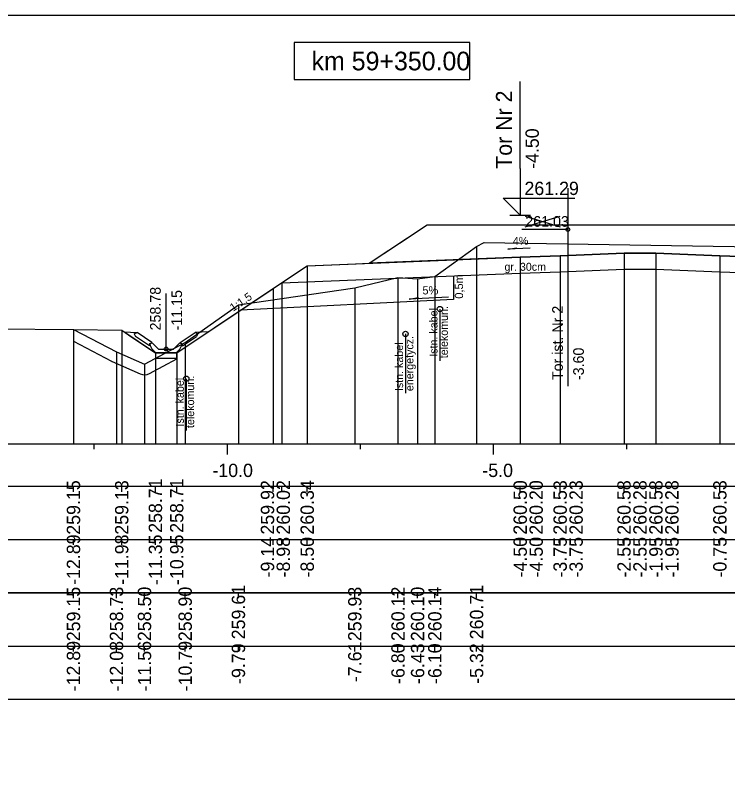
# Model space of a CAD drawing. Extents: x 6516023 to 6560129, y 5513077 to 5529206.
# Drawn here: x 6517566.48 to 6517579.86, y 5514532.41 to 5514546.66 of the extents above; entities that cross this region are included whole.
import ezdxf

# ---------------------------------------------------------------- set-up
doc = ezdxf.new("R2010")
doc.units = 0
for name, color, linetype in [('IR_default', 7, 'Continuous'), ('TOR_PRZEK_P-kable', 7, 'Continuous'), ('TOR_PRZEK_P-komponent', 7, 'Continuous'), ('TOR_PRZEK_P-odwodnienie', 7, 'Continuous'), ('TOR_PRZEK_P-opisy', 7, 'Continuous'), ('TOR_PRZEK_P-schodkowanie+wymiana', 7, 'Continuous'), ('TOR_PRZEK_P-tabelka istniejace', 7, 'Continuous'), ('TOR_PRZEK_P-tabelka projektowane', 7, 'Continuous'), ('TOR_PRZEK_P-teren istniejacy', 7, 'Continuous'), ('TOR_PRZEK_P-tory istniejace', 7, 'Continuous'), ('TOR_PRZEK_P-tory projektowane', 7, 'Continuous'), ('TOR_PRZEK_P-uklad odniesienia', 7, 'Continuous'), ('TOR_PRZEK_P-warstwa ochronna I', 7, 'Continuous'), ('TOR_PRZEK_P-warstwa ochronna II', 7, 'Continuous'), ('TOR_PS_T-skarpy projektowane', 7, 'Continuous'), ('TOR_RAMKI-ramka+tabelka 1', 7, 'Continuous')]:
    doc.layers.add(name, color=color, linetype=linetype)

msp = doc.modelspace()

# ---------------------------------------------------------------- linework, layer by layer
at = {"layer": 'IR_default'}
msp.add_lwpolyline([(6517567.573, 5514540.755), (6517568.479, 5514540.737), (6517568.604, 5514540.653), (6517568.728, 5514540.571), (6517569.112, 5514540.315), (6517569.422, 5514540.315), (6517569.512, 5514540.315), (6517570.919, 5514541.253), (6517571.323, 5514541.523), (6517571.324, 5514541.523), (6517571.325, 5514541.523), (6517571.82, 5514541.853), (6517571.963, 5514541.948), (6517572.867, 5514541.984), (6517573.128, 5514541.995), (6517573.97, 5514542.556), (6517574.213, 5514542.718), (6517576.929, 5514542.718), (6517577.713, 5514542.718), (6517578.489, 5514542.718), (6517578.713, 5514542.718), (6517581.429, 5514542.718)], dxfattribs=at)
at = {"layer": 'TOR_PRZEK_P-kable'}
for p, q in [((6517574.455, 5514541.137), (6517574.455, 5514540.164)), ((6517573.809, 5514540.669), (6517573.809, 5514539.559)), ((6517569.691, 5514539.828), (6517569.691, 5514538.854))]:
    msp.add_line(p, q, dxfattribs=at)
for centre in [(6517574.455, 5514541.137), (6517573.809, 5514540.669), (6517569.691, 5514539.828)]:
    msp.add_circle(centre, 0.05, dxfattribs=at)
at = {"layer": 'TOR_PRZEK_P-komponent'}
msp.add_lwpolyline([(6517574.213, 5514542.718), (6517577.713, 5514542.718), (6517578.713, 5514542.718), (6517582.213, 5514542.718), (6517582.763, 5514542.719), (6517586.263, 5514542.719), (6517587.608, 5514541.822), (6517583.763, 5514541.976), (6517580.463, 5514542.108), (6517579.713, 5514542.138), (6517578.513, 5514542.186), (6517577.913, 5514542.186), (6517576.713, 5514542.138), (6517575.963, 5514542.108), (6517573.128, 5514541.995)], close=True, dxfattribs=at)
at = {"layer": 'TOR_PRZEK_P-odwodnienie'}
for p, q in [((6517569.312, 5514540.385), (6517569.312, 5514541.429)), ((6517569.047, 5514540.511), (6517568.767, 5514540.698)), ((6517569.576, 5514540.511), (6517569.857, 5514540.698)), ((6517569.003, 5514540.444), (6517568.741, 5514540.618)), ((6517569.621, 5514540.444), (6517569.882, 5514540.618)), ((6517569.014, 5514540.461), (6517569.003, 5514540.444)), ((6517569.004, 5514540.48), (6517569.052, 5514540.504)), ((6517569.047, 5514540.511), (6517569.039, 5514540.498)), ((6517569.172, 5514540.385), (6517569.052, 5514540.504)), ((6517569.172, 5514540.385), (6517569.452, 5514540.385)), ((6517569.452, 5514540.385), (6517569.572, 5514540.504)), ((6517569.572, 5514540.504), (6517569.619, 5514540.48)), ((6517569.576, 5514540.511), (6517569.585, 5514540.498)), ((6517569.61, 5514540.461), (6517569.621, 5514540.444)), ((6517569.122, 5514540.315), (6517569.502, 5514540.315))]:
    msp.add_line(p, q, dxfattribs=at)
for points in [[(6517568.52, 5514540.709), (6517568.767, 5514540.698)], [(6517568.716, 5514540.671), (6517568.767, 5514540.698)], [(6517568.716, 5514540.671), (6517568.741, 5514540.618)], [(6517570.103, 5514540.709), (6517569.857, 5514540.698)], [(6517569.907, 5514540.671), (6517569.857, 5514540.698)], [(6517569.907, 5514540.671), (6517569.882, 5514540.618)], [(6517569.039, 5514540.498), (6517569.004, 5514540.48)], [(6517569.052, 5514540.385), (6517569.004, 5514540.48)], [(6517569.004, 5514540.48), (6517569.014, 5514540.461)], [(6517569.122, 5514540.315), (6517569.052, 5514540.385)], [(6517569.502, 5514540.315), (6517569.572, 5514540.385)], [(6517569.572, 5514540.385), (6517569.619, 5514540.48)], [(6517569.585, 5514540.498), (6517569.62, 5514540.48)], [(6517569.62, 5514540.48), (6517569.61, 5514540.461)], [(6517569.512, 5514540.315), (6517569.112, 5514540.315), (6517569.112, 5514540.215), (6517569.512, 5514540.215), (6517569.512, 5514540.315)], [(6517569.512, 5514540.315), (6517569.511, 5514540.316), (6517569.512, 5514540.315), (6517569.511, 5514540.315), (6517569.512, 5514540.315), (6517569.512, 5514540.315), (6517569.512, 5514540.315), (6517569.512, 5514540.316)], [(6517569.512, 5514540.315), (6517569.511, 5514540.315), (6517569.512, 5514540.315), (6517569.511, 5514540.314), (6517569.512, 5514540.315), (6517569.512, 5514540.314), (6517569.512, 5514540.315), (6517569.512, 5514540.315)]]:
    msp.add_lwpolyline(points, dxfattribs=at)
msp.add_circle((6517569.312, 5514540.385), 0.035, dxfattribs=at)
at = {"layer": 'TOR_PRZEK_P-opisy'}
msp.add_lwpolyline([(6517576.149, 5514542.277), (6517575.731, 5514542.258), (6517575.899, 5514542.286)], dxfattribs=at)
at = {"layer": 'TOR_PRZEK_P-schodkowanie+wymiana'}
for p, q in [((6517574.708, 5514541.758), (6517574.708, 5514541.315)), ((6517574.708, 5514541.315), (6517570.712, 5514541.115)), ((6517568.301, 5514540.151), (6517568.826, 5514539.92)), ((6517569.001, 5514539.926), (6517569.512, 5514540.199))]:
    msp.add_line(p, q, dxfattribs=at)
msp.add_lwpolyline([(6517567.573, 5514540.53), (6517568.289, 5514540.156)], dxfattribs=at)
for centre, start, end in [((6517568.381, 5514540.334), 242.4451, 246.2607), ((6517568.907, 5514540.103), 246.2607, 298.0902)]:
    msp.add_arc(centre, 0.2, start, end, dxfattribs=at)
at = {"layer": 'TOR_PRZEK_P-tabelka istniejace'}
for p, q in [((6517567.573, 5514535.706), (6517567.573, 5514535.806)), ((6517568.381, 5514535.706), (6517568.381, 5514535.806)), ((6517568.907, 5514535.706), (6517568.907, 5514535.806)), ((6517569.671, 5514535.706), (6517569.671, 5514535.806)), ((6517570.671, 5514535.706), (6517570.671, 5514535.806)), ((6517572.857, 5514535.706), (6517572.857, 5514535.806)), ((6517573.668, 5514535.706), (6517573.668, 5514535.806)), ((6517574.036, 5514535.706), (6517574.036, 5514535.806)), ((6517574.36, 5514535.706), (6517574.36, 5514535.806)), ((6517575.144, 5514535.706), (6517575.144, 5514535.806)), ((6517541.663, 5514534.806), (6517625.463, 5514534.806)), ((6517567.573, 5514534.706), (6517567.573, 5514534.806)), ((6517568.381, 5514534.706), (6517568.381, 5514534.806)), ((6517568.907, 5514534.706), (6517568.907, 5514534.806)), ((6517569.671, 5514534.706), (6517569.671, 5514534.806)), ((6517570.671, 5514534.706), (6517570.671, 5514534.806)), ((6517572.857, 5514534.706), (6517572.857, 5514534.806)), ((6517573.668, 5514534.706), (6517573.668, 5514534.806)), ((6517574.036, 5514534.706), (6517574.036, 5514534.806)), ((6517574.36, 5514534.706), (6517574.36, 5514534.806)), ((6517575.144, 5514534.706), (6517575.144, 5514534.806))]:
    msp.add_line(p, q, dxfattribs=at)
for points in [[(6517575.144, 5514542.314), (6517575.144, 5514538.806), (6517575.144, 5514538.676), (6517575.144, 5514538.606)], [(6517573.668, 5514541.73), (6517573.668, 5514538.806), (6517573.668, 5514538.676), (6517573.668, 5514538.606)], [(6517574.036, 5514541.703), (6517574.036, 5514538.806), (6517574.036, 5514538.676), (6517574.036, 5514538.606)], [(6517574.36, 5514541.745), (6517574.36, 5514538.806), (6517574.36, 5514538.676), (6517574.36, 5514538.606)], [(6517572.857, 5514541.536), (6517572.857, 5514538.806), (6517572.857, 5514538.676), (6517572.857, 5514538.606)], [(6517570.671, 5514541.215), (6517570.671, 5514538.806), (6517570.671, 5514538.676), (6517570.671, 5514538.606)], [(6517567.573, 5514540.755), (6517567.573, 5514538.806), (6517567.573, 5514538.676), (6517567.573, 5514538.606)], [(6517569.671, 5514540.51), (6517569.671, 5514538.806), (6517569.671, 5514538.676), (6517569.671, 5514538.606)], [(6517568.381, 5514540.334), (6517568.381, 5514538.806), (6517568.381, 5514538.676), (6517568.381, 5514538.606)], [(6517568.907, 5514540.103), (6517568.907, 5514538.806), (6517568.907, 5514538.676), (6517568.907, 5514538.606)]]:
    msp.add_lwpolyline(points, dxfattribs=at)
msp.add_lwpolyline([(6517541.663, 5514535.806), (6517541.663, 5514533.806), (6517625.463, 5514533.806), (6517625.463, 5514535.806)], close=True, dxfattribs=at)
at = {"layer": 'TOR_PRZEK_P-tabelka projektowane'}
for p, q in [((6517567.573, 5514537.706), (6517567.573, 5514537.806)), ((6517568.479, 5514537.706), (6517568.479, 5514537.806)), ((6517569.112, 5514537.706), (6517569.112, 5514537.806)), ((6517569.512, 5514537.706), (6517569.512, 5514537.806)), ((6517571.323, 5514537.706), (6517571.323, 5514537.806)), ((6517571.484, 5514537.706), (6517571.484, 5514537.806)), ((6517571.963, 5514537.706), (6517571.963, 5514537.806)), ((6517575.963, 5514537.706), (6517575.963, 5514537.806)), ((6517575.963, 5514537.706), (6517575.963, 5514537.806)), ((6517576.713, 5514537.706), (6517576.713, 5514537.806)), ((6517576.713, 5514537.706), (6517576.713, 5514537.806)), ((6517577.913, 5514537.706), (6517577.913, 5514537.806)), ((6517577.913, 5514537.706), (6517577.913, 5514537.806)), ((6517578.513, 5514537.706), (6517578.513, 5514537.806)), ((6517578.513, 5514537.706), (6517578.513, 5514537.806)), ((6517579.713, 5514537.706), (6517579.713, 5514537.806)), ((6517579.713, 5514537.706), (6517579.713, 5514537.806)), ((6517541.663, 5514536.806), (6517625.463, 5514536.806)), ((6517567.573, 5514536.706), (6517567.573, 5514536.806)), ((6517568.479, 5514536.706), (6517568.479, 5514536.806)), ((6517569.112, 5514536.706), (6517569.112, 5514536.806)), ((6517569.512, 5514536.706), (6517569.512, 5514536.806)), ((6517571.323, 5514536.706), (6517571.323, 5514536.806)), ((6517571.484, 5514536.706), (6517571.484, 5514536.806)), ((6517571.963, 5514536.706), (6517571.963, 5514536.806)), ((6517575.963, 5514536.706), (6517575.963, 5514536.806)), ((6517575.963, 5514536.706), (6517575.963, 5514536.806)), ((6517576.713, 5514536.706), (6517576.713, 5514536.806)), ((6517576.713, 5514536.706), (6517576.713, 5514536.806)), ((6517577.913, 5514536.706), (6517577.913, 5514536.806)), ((6517577.913, 5514536.706), (6517577.913, 5514536.806)), ((6517578.513, 5514536.706), (6517578.513, 5514536.806)), ((6517578.513, 5514536.706), (6517578.513, 5514536.806)), ((6517579.713, 5514536.706), (6517579.713, 5514536.806)), ((6517579.713, 5514536.706), (6517579.713, 5514536.806))]:
    msp.add_line(p, q, dxfattribs=at)
for points in [[(6517575.963, 5514542.108), (6517575.963, 5514538.806), (6517575.963, 5514538.676), (6517575.963, 5514538.606)], [(6517576.713, 5514542.138), (6517576.713, 5514538.806), (6517576.713, 5514538.676), (6517576.713, 5514538.606)], [(6517577.913, 5514542.186), (6517577.913, 5514538.806), (6517577.913, 5514538.676), (6517577.913, 5514538.606)], [(6517578.513, 5514542.186), (6517578.513, 5514538.806), (6517578.513, 5514538.676), (6517578.513, 5514538.606)], [(6517579.713, 5514542.138), (6517579.713, 5514538.806), (6517579.713, 5514538.676), (6517579.713, 5514538.606)], [(6517571.963, 5514541.948), (6517571.963, 5514538.806), (6517571.963, 5514538.676), (6517571.963, 5514538.606)], [(6517575.963, 5514541.808), (6517575.963, 5514538.806), (6517575.963, 5514538.676), (6517575.963, 5514538.606)], [(6517576.713, 5514541.838), (6517576.713, 5514538.806), (6517576.713, 5514538.676), (6517576.713, 5514538.606)], [(6517577.913, 5514541.886), (6517577.913, 5514538.806), (6517577.913, 5514538.676), (6517577.913, 5514538.606)], [(6517578.513, 5514541.886), (6517578.513, 5514538.806), (6517578.513, 5514538.676), (6517578.513, 5514538.606)], [(6517579.713, 5514541.838), (6517579.713, 5514538.806), (6517579.713, 5514538.676), (6517579.713, 5514538.606)], [(6517571.484, 5514541.629), (6517571.484, 5514538.806), (6517571.484, 5514538.676), (6517571.484, 5514538.606)], [(6517571.323, 5514541.522), (6517571.323, 5514538.806), (6517571.323, 5514538.676), (6517571.323, 5514538.606)], [(6517567.573, 5514540.755), (6517567.573, 5514538.806), (6517567.573, 5514538.676), (6517567.573, 5514538.606)], [(6517568.479, 5514540.737), (6517568.479, 5514538.806), (6517568.479, 5514538.676), (6517568.479, 5514538.606)], [(6517569.112, 5514540.315), (6517569.112, 5514538.806), (6517569.112, 5514538.676), (6517569.112, 5514538.606)], [(6517569.512, 5514540.315), (6517569.512, 5514538.806), (6517569.512, 5514538.676), (6517569.512, 5514538.606)]]:
    msp.add_lwpolyline(points, dxfattribs=at)
msp.add_lwpolyline([(6517541.663, 5514537.806), (6517541.663, 5514535.806), (6517625.463, 5514535.806), (6517625.463, 5514537.806)], close=True, dxfattribs=at)
at = {"layer": 'TOR_PRZEK_P-teren istniejacy'}
msp.add_lwpolyline([(6517564.672, 5514540.777), (6517567.573, 5514540.755), (6517568.381, 5514540.334), (6517568.907, 5514540.103), (6517569.671, 5514540.51), (6517570.671, 5514541.215), (6517572.857, 5514541.536), (6517573.668, 5514541.73), (6517574.036, 5514541.703), (6517574.36, 5514541.745), (6517575.144, 5514542.314), (6517575.285, 5514542.385), (6517585.065, 5514542.229), (6517586.264, 5514542.238), (6517586.947, 5514542.077), (6517587.027, 5514542.084), (6517587.689, 5514542.093), (6517589.317, 5514542.001), (6517591.409, 5514540.794), (6517592.192, 5514540.454), (6517598.106, 5514540.709)], dxfattribs=at)
at = {"layer": 'TOR_PRZEK_P-tory istniejace'}
for p, q in [((6517576.858, 5514543.407), (6517576.858, 5514539.687)), ((6517576.059, 5514542.679), (6517576.711, 5514542.882)), ((6517576.059, 5514542.882), (6517576.711, 5514542.679)), ((6517576.859, 5514542.632), (6517575.993, 5514542.632))]:
    msp.add_line(p, q, dxfattribs=at)
msp.add_circle((6517576.859, 5514542.632), 0.035, dxfattribs=at)
at = {"layer": 'TOR_PRZEK_P-tory projektowane'}
for p, q in [((6517575.963, 5514543.776), (6517575.963, 5514545.408)), ((6517575.963, 5514543.776), (6517575.963, 5514542.898)), ((6517575.963, 5514542.898), (6517575.644, 5514543.217)), ((6517575.644, 5514543.217), (6517576.988, 5514543.217)), ((6517575.771, 5514542.898), (6517576.155, 5514542.898))]:
    msp.add_line(p, q, dxfattribs=at)
at = {"layer": 'TOR_PRZEK_P-uklad odniesienia'}
for p, q in [((6517545.463, 5514538.606), (6517625.463, 5514538.606)), ((6517567.963, 5514538.506), (6517567.963, 5514538.606)), ((6517570.463, 5514538.406), (6517570.463, 5514538.606)), ((6517572.963, 5514538.506), (6517572.963, 5514538.606)), ((6517575.463, 5514538.406), (6517575.463, 5514538.606)), ((6517577.963, 5514538.506), (6517577.963, 5514538.606))]:
    msp.add_line(p, q, dxfattribs=at)
msp.add_lwpolyline([(6517575.017, 5514546.145), (6517571.717, 5514546.145), (6517571.717, 5514545.445), (6517575.017, 5514545.445)], close=True, dxfattribs=at)
at = {"layer": 'TOR_PRZEK_P-warstwa ochronna I'}
msp.add_lwpolyline([(6517571.484, 5514541.629), (6517575.963, 5514541.808), (6517576.713, 5514541.838), (6517577.913, 5514541.886), (6517578.513, 5514541.886), (6517579.713, 5514541.838), (6517580.463, 5514541.808), (6517583.763, 5514541.676), (6517584.513, 5514541.646), (6517589.465, 5514541.448)], dxfattribs=at)
at = {"layer": 'TOR_PRZEK_P-warstwa ochronna II'}
msp.add_lwpolyline([(6517567.573, 5514540.755), (6517568.479, 5514540.737), (6517569.112, 5514540.315), (6517569.512, 5514540.315), (6517571.323, 5514541.522), (6517571.325, 5514541.523), (6517571.963, 5514541.948), (6517575.963, 5514542.108), (6517576.713, 5514542.138), (6517577.913, 5514542.186), (6517578.513, 5514542.186), (6517579.713, 5514542.138), (6517580.463, 5514542.108), (6517583.763, 5514541.976), (6517584.513, 5514541.946), (6517588.813, 5514541.774), (6517589.682, 5514541.339), (6517592.271, 5514540.045), (6517592.671, 5514540.045), (6517593.36, 5514540.505)], dxfattribs=at)
at = {"layer": 'TOR_PS_T-skarpy projektowane'}
msp.add_lwpolyline([(6517574.615, 5514541.359), (6517573.88, 5514541.32), (6517574.053, 5514541.351)], dxfattribs=at)
at = {"layer": 'TOR_RAMKI-ramka+tabelka 1'}
msp.add_lwpolyline([(6517452.013, 5514546.656), (6517699.513, 5514546.656), (6517699.513, 5514518.156), (6517452.013, 5514518.156)], close=True, dxfattribs=at)

# ---------------------------------------------------------------- texts
at = {"layer": 'TOR_PRZEK_P-kable'}
for s, height, p in [('Istn. kabel', 0.14999, (6517574.41, 5514540.24)), ('telekomun.', 0.15, (6517574.605, 5514540.212)), ('energetycz.', 0.14999, (6517573.958, 5514539.595)), ('Istn. kabel', 0.14999, (6517573.764, 5514539.595)), ('Istn. kabel', 0.14999, (6517569.646, 5514538.93)), ('telekomun.', 0.15, (6517569.84, 5514538.902))]:
    msp.add_text(s, height=height, rotation=90.0511, dxfattribs=at).set_placement(p)
at = {"layer": 'TOR_PRZEK_P-odwodnienie'}
for s, p in [('258.78', (6517569.212, 5514540.735)), ('-11.15', (6517569.612, 5514540.735))]:
    msp.add_text(s, height=0.2, rotation=90, dxfattribs=at).set_placement(p)
at = {"layer": 'TOR_PRZEK_P-opisy'}
for s, rotation, p in [('4%', 0.1515, (6517575.826, 5514542.342)), ('1:1,5', 34.0701, (6517570.572, 5514541.084))]:
    msp.add_text(s, height=0.15, rotation=rotation, dxfattribs=at).set_placement(p)
at = {"layer": 'TOR_PRZEK_P-schodkowanie+wymiana'}
msp.add_text('0,5m', height=0.1545, rotation=90, dxfattribs=at).set_placement((6517574.89, 5514541.331))
at = {"layer": 'TOR_PRZEK_P-tabelka istniejace'}
for s, p in [('259.15', (6517567.698, 5514534.897)), ('258.73', (6517568.506, 5514534.898)), ('258.50', (6517569.032, 5514534.898)), ('258.90', (6517569.796, 5514534.898)), ('259.61', (6517570.796, 5514534.933)), ('259.93', (6517572.982, 5514534.898)), ('260.12', (6517573.793, 5514534.9)), ('260.10', (6517574.161, 5514534.898)), ('260.14', (6517574.485, 5514534.899)), ('260.71', (6517575.269, 5514534.933)), ('-12.89', (6517567.698, 5514533.955)), ('-12.08', (6517568.506, 5514533.954)), ('-11.56', (6517569.032, 5514533.954)), ('-10.79', (6517569.796, 5514533.955)), ('-9.79', (6517570.796, 5514534.094)), ('-7.61', (6517572.982, 5514534.129)), ('-6.80', (6517573.793, 5514534.094)), ('-6.43', (6517574.161, 5514534.094)), ('-6.10', (6517574.485, 5514534.094)), ('-5.32', (6517575.269, 5514534.096))]:
    msp.add_text(s, height=0.25, rotation=90, dxfattribs=at).set_placement(p)
at = {"layer": 'TOR_PRZEK_P-tabelka projektowane'}
for s, p in [('259.15', (6517567.698, 5514536.897)), ('259.13', (6517568.604, 5514536.898)), ('258.71', (6517569.237, 5514536.933)), ('258.71', (6517569.637, 5514536.933)), ('259.92', (6517571.342, 5514536.9)), ('260.02', (6517571.639, 5514536.9)), ('260.34', (6517572.088, 5514536.899)), ('260.50', (6517576.088, 5514536.898)), ('260.20', (6517576.388, 5514536.898)), ('260.53', (6517576.838, 5514536.898)), ('260.23', (6517577.138, 5514536.898)), ('260.58', (6517578.038, 5514536.898)), ('260.28', (6517578.338, 5514536.898)), ('260.58', (6517578.638, 5514536.898)), ('260.28', (6517578.938, 5514536.898)), ('260.53', (6517579.838, 5514536.898)), ('-12.89', (6517567.698, 5514535.955)), ('-11.98', (6517568.604, 5514535.954)), ('-11.35', (6517569.237, 5514535.953)), ('-10.95', (6517569.637, 5514535.953)), ('-9.14', (6517571.342, 5514536.095)), ('-8.98', (6517571.639, 5514536.094)), ('-8.50', (6517572.088, 5514536.094)), ('-4.50', (6517576.088, 5514536.094)), ('-4.50', (6517576.388, 5514536.094)), ('-3.75', (6517576.838, 5514536.093)), ('-3.75', (6517577.138, 5514536.093)), ('-2.55', (6517578.038, 5514536.093)), ('-2.55', (6517578.338, 5514536.093)), ('-1.95', (6517578.638, 5514536.093)), ('-1.95', (6517578.938, 5514536.093)), ('-0.75', (6517579.838, 5514536.093))]:
    msp.add_text(s, height=0.25, rotation=90, dxfattribs=at).set_placement(p)
at = {"layer": 'TOR_PRZEK_P-tory istniejace'}
msp.add_text('261.03', height=0.2, dxfattribs=at).set_placement((6517576.059, 5514542.682))
for s, rotation, p in [('Tor ist. Nr 2', 90.0511, (6517576.765, 5514539.802)), ('-3.60', 90, (6517577.159, 5514539.802))]:
    msp.add_text(s, height=0.2, rotation=rotation, dxfattribs=at).set_placement(p)
at = {"layer": 'TOR_PRZEK_P-tory projektowane'}
for s, height, p in [('Tor Nr 2', 0.3, (6517575.808, 5514543.77)), ('-4.50', 0.25, (6517576.313, 5514543.768))]:
    msp.add_text(s, height=height, rotation=90, dxfattribs=at).set_placement(p)
msp.add_text('261.29', height=0.25, dxfattribs=at).set_placement((6517576.043, 5514543.278))
at = {"layer": 'TOR_PRZEK_P-uklad odniesienia'}
for s, height, p in [('km 59+350.00', 0.35, (6517572.045, 5514545.62)), ('-10.0', 0.25, (6517570.182, 5514537.981)), ('-5.0', 0.25, (6517575.252, 5514537.981))]:
    msp.add_text(s, height=height, dxfattribs=at).set_placement(p)
at = {"layer": 'TOR_PRZEK_P-warstwa ochronna I'}
msp.add_text('gr. 30cm', height=0.15, dxfattribs=at).set_placement((6517575.668, 5514541.855))
at = {"layer": 'TOR_PS_T-skarpy projektowane'}
msp.add_text('5%', height=0.1545, dxfattribs=at).set_placement((6517574.127, 5514541.411))

doc.saveas('drawing.dxf')
